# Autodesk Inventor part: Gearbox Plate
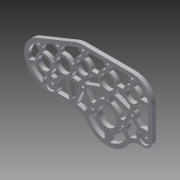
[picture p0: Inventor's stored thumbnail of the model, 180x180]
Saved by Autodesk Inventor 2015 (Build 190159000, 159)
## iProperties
Created: 2014-11
Part Number: Gearbox Plate
Material: Aluminum 6061
Document SubType Name: Sheet Metal
Designer: Michael
Density: 2.71 g/cm^3
Appearance: Aluminum - Flat
Sheet Metal Rule: Default
Mass: 155.766 g
Surface Area: 356.193 cm^2
Volume: 57.4784 cm^3
Author: Michael
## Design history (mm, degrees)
node "Face1"
  sketch "Sketch1" dims "d12" = 63.5 (= DrivenGear), "d35" = 22.352, "d96" = 4.2545 (derived)
    geometry: L1 (-39.37, 48.336)-(0, 48.336); L2 (0, 0)-(0, 48.336); L3 (0, 0)-(-38.1, 0); L4 (0, 48.336)-(-31.75, 48.336); L5 (-110.258, 47.105)-(-91.237, 0); L6 (-112.73, 53.228)-(-51.353, 78.012); L7 (-39.37, 80.34)-(39.37, 80.34); L8 (-100.747, 23.552)-(-39.37, 48.336); L9 (71.374, 48.336)-(71.374, 0); L10 (58.674, -12.7)-(52.771, -12.7); L11 (-91.237, -12.86)-(-52.655, -12.86); L12 (39.37, 80.34)-(-39.37, 80.34); L13 (-51.353, 78.012)-(-112.73, 53.228); L14 (-91.237, -12.86)-(-52.655, -12.86); L15 (58.674, -12.7)-(55.722, -12.7); L16 (71.374, 0)-(71.374, 48.336); L17 (-52.655, -12.86)-(-91.237, -12.86); L18 (52.771, -12.7)-(58.674, -12.7); L19 (-110.258, 47.105)-(-100.061, 21.852); L20 (-70.059, 35.944)-(-82.042, 65.62); L21 (-39.37, 48.336)-(-39.37, 73.736); L22 (-39.37, 48.336)-(-39.37, 22.936); L23 (0, 48.336)-(39.37, 48.336); L24 (39.37, 48.336)-(39.37, 73.736); L25 (39.37, 22.936)-(39.37, 48.336); L26 (39.37, 48.336)-(71.374, 48.336); L27 (0, 0)-(0, -39.688); L28 (-91.237, 0)-(-65.874, 25.581); L29 (-65.874, 25.581)-(-55.574, -12.86); L30 (-39.37, 22.936)-(-55.574, -12.86); L31 (39.37, 22.936)-(23.812, 0); L32 (-39.37, 22.936)-(-23.812, 0); L33 (-100.747, 23.552)-(-130.423, 11.569); L34 (-108.474, 35.267)-(-103.322, 37.348); L35 (-103.322, 37.348)-(-105.174, 41.934); L36 (-105.174, 41.934)-(-110.326, 39.853); L37 (-110.326, 39.853)-(-108.474, 35.267); L38 (-114.543, 20.978)-(-112.462, 15.826); L39 (-112.462, 15.826)-(-129.383, 8.993); L40 (-129.383, 8.993)-(-131.464, 14.145); L41 (-131.464, 14.145)-(-114.543, 20.978); L42 (-81.113, 6.266)-(-85.059, 10.178); L43 (-85.059, 10.178)-(-70.542, 24.819); L44 (-70.542, 24.819)-(-66.596, 20.907); L45 (-66.596, 20.907)-(-81.113, 6.266); L46 (-67.452, 20.736)-(-62.085, 22.174); L47 (-62.085, 22.174)-(-52.698, -12.86); L48 (-52.698, -12.86)-(-58.065, -14.298); L49 (-58.065, -14.298)-(-67.452, 20.736); L50 (-39.37, 73.99)-(39.37, 73.99); L51 (65.024, 0)-(65.024, 48.336); L52 (58.674, -6.35)-(52.771, -6.35); L53 (-91.237, -6.51)-(-52.655, -6.51); L54 (-115.367, 45.316)-(-48.975, 72.124); L55 (-58.623, -12.86)-(-53.562, -15.151); L56 (-53.562, -15.151)-(-39.601, 15.688); L57 (-39.601, 15.688)-(-44.663, 17.98); L58 (-44.663, 17.98)-(-58.623, -12.86); L59 (-89.033, 31.279)-(-86.952, 26.127); L60 (-86.952, 26.127)-(-83.093, 27.685); L61 (-83.093, 27.685)-(-85.173, 32.837); L62 (-85.173, 32.837)-(-89.033, 31.279); L63 (-78.318, 48.978)-(-73.166, 51.059); L64 (-73.166, 51.059)-(-79.466, 66.66)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; C1 r 25.4 at (0, 0); C2 r 22.86 at (0, 48.336); C3 r 7.62 at (-39.37, 48.336); C4 r 7.62 at (39.37, 48.336); C5 r 10.16 at (0, 48.336); C6 r 13.5 at (0, 0); C7 r 2.489 at (-91.237, 0); C8 r 2.489 at (-110.258, 47.105); C9 r 7.62 at (-100.747, 23.552); C10 r 25.4 at (-70.059, 35.944); C11 r 9.525 at (-91.237, 0); C12 r 9.779 at (-100.747, 23.552); C13 r 9.779 at (-39.37, 48.336); C14 r 9.779 at (39.37, 48.336); C15 r 11.176 at (0, 48.336); C16 r 14.351 at (0, 0); C17 r 9.525 at (58.674, 0); C18 r 2.489 at (-39.37, 22.936); C19 r 2.489 at (-39.37, 73.736); C20 r 2.489 at (39.37, 73.736); C21 r 2.489 at (39.37, 22.936); C22 r 2.489 at (58.674, 0); C23 r 2.489 at (-23.812, 0); C24 r 2.489 at (23.812, 0); C25 r 1.587 at (20.206, -6.735); C26 r 1.587 at (-20.206, -6.735); C27 r 1.587 at (0, 23.244); C28 r 2.489 at (0, 73.99); C29 r 2.489 at (-79.664, 59.732); C30 r 6.35 at (0, 73.99); C31 r 6.35 at (-79.664, 59.732); A1 r 38.1 centre (0, 0) between (-38.1, 0) and (-30.706, -22.555); A2 r 32.004 centre (-39.37, 48.336) between (-51.353, 78.012) and (-39.37, 80.34); A3 r 32.004 centre (39.37, 48.336) between (39.37, 80.34) and (71.374, 48.336); A4 r 32.004 centre (-100.747, 23.552) between (-112.73, 53.228) and (-125.169, 2.868); A5 r 12.7 centre (58.674, 0) between (58.674, -12.7) and (71.374, 0); A6 r 44.467 centre (-91.237, 31.607) between (-125.169, 2.868) and (-91.237, -12.86); A7 r 32.004 centre (-39.37, 48.336) between (-39.37, 80.34) and (-51.353, 78.012); A8 r 32.004 centre (-100.747, 23.552) between (-112.73, 53.228) and (-125.169, 2.868); A9 r 44.467 centre (-91.237, 31.607) between (-125.169, 2.868) and (-91.237, -12.86); A10 r 12.7 centre (58.674, 0) between (58.674, -12.7) and (71.374, 0); A11 r 32.004 centre (39.37, 48.336) between (71.374, 48.336) and (39.37, 80.34); A12 r 39.688 centre (0, 0) between (-32.107, -23.329) and (32.177, -23.232); A13 r 25.4 centre (-52.655, -38.26) between (-32.107, -23.329) and (-52.655, -12.86); A14 r 25.4 centre (52.771, -38.1) between (52.771, -12.7) and (32.177, -23.232); A15 r 25.4 centre (-52.655, -38.26) between (-32.107, -23.329) and (-52.655, -12.86); A16 r 39.687 centre (0, 0) between (-32.107, -23.329) and (32.177, -23.232); A17 r 25.4 centre (52.771, -38.1) between (52.771, -12.7) and (32.177, -23.232); A18 r 11.906 centre (-91.237, 0) between (-81.113, 6.266) and (-85.059, 10.178); A19 r 7.252 centre (-110.258, 47.105) between (-105.174, 41.934) and (-116.651, 43.682); A20 r 14.034 centre (-39.37, 48.336) between (-53.165, 45.762) and (-42.148, 62.092); A21 r 7.252 centre (-39.37, 73.736) between (-36.592, 67.038) and (-46.58, 72.956); A22 r 7.252 centre (39.37, 73.736) between (42.148, 67.038) and (32.123, 73.99); A23 r 14.034 centre (39.37, 48.336) between (25.614, 51.114) and (36.592, 62.092); A24 r 8.045 centre (-23.812, 0) between (-31.194, -3.199) and (-24.856, -7.977); A25 r 8.045 centre (23.812, 0) between (24.888, -7.973) and (31.207, -3.17); A26 r 12.7 centre (58.674, 0) between (53.185, 11.453) and (65.024, 10.999); A27 r 7.252 centre (39.37, 22.936) between (36.592, 29.635) and (42.148, 29.635); A28 r 25.654 centre (39.37, 48.336) between (65.024, 48.336) and (39.37, 73.99); A29 r 6.35 centre (58.674, 0) between (58.674, -6.35) and (65.024, 0); A30 r 31.75 centre (52.771, -38.1) between (52.771, -6.35) and (27.029, -19.515); A31 r 33.338 centre (0, 0) between (-26.97, -19.596) and (27.029, -19.515); A32 r 31.75 centre (-52.655, -38.26) between (-26.97, -19.596) and (-52.655, -6.51); A33 r 38.117 centre (-91.237, 31.607) between (-120.324, 6.972) and (-91.237, -6.51); A34 r 25.654 centre (-100.747, 23.552) between (-109.26, 47.753) and (-120.324, 6.972); A35 r 25.654 centre (-39.37, 48.336) between (-39.37, 73.99) and (-48.975, 72.124); A36 r 6.35 centre (-79.664, 59.732) between (-85.552, 57.355) and (-80.102, 53.397); A37 r 6.35 centre (0, 73.99) between (2.778, 68.28) and (-6.35, 73.99); A38 r 38.117 centre (-90.968, 31.526) between (-123.355, 11.427) and (-102.071, -4.938); A39 r 11.906 centre (-91.237, 0) between (-98.148, 9.695) and (-102.071, -4.938); A40 r 14.034 centre (-100.747, 23.552) between (-112.462, 15.826) and (-98.173, 9.757); A41 r 14.034 centre (-100.747, 23.552) between (-108.474, 35.267) and (-114.543, 20.978); A42 r 7.252 centre (-110.258, 47.105) between (-116.651, 43.682) and (-110.326, 39.853); A43 r 25.654 centre (-100.747, 23.552) between (-116.651, 43.682) and (-125.436, 16.58); A44 r 14.034 centre (-100.747, 23.552) between (-89.033, 31.279) and (-103.322, 37.348); A45 r 7.252 centre (-110.258, 47.105) between (-105.174, 41.934) and (-103.633, 50.054); A46 r 15.431 centre (-70.059, 35.944) between (-78.318, 48.978) and (-85.173, 32.837); A47 r 6.35 centre (-79.664, 59.732) between (-85.552, 57.355) and (-80.102, 53.397); A48 r 14.034 centre (-100.747, 23.552) between (-93.021, 11.837) and (-86.952, 26.127); A49 r 15.431 centre (-70.059, 35.944) between (-83.093, 27.685) and (-74.239, 21.091); A50 r 11.906 centre (-91.237, 0) between (-85.059, 10.178) and (-92.996, 11.776); A51 r 11.906 centre (-91.237, 0) between (-81.268, -6.51) and (-81.113, 6.266); A52 r 15.431 centre (-70.059, 35.944) between (-57.025, 44.203) and (-73.166, 51.059); A53 r 6.35 centre (-79.664, 59.732) between (-74.95, 55.478) and (-73.776, 62.11); A54 r 14.034 centre (-39.37, 48.336) between (-42.148, 62.092) and (-53.165, 45.762); A55 r 7.252 centre (-39.37, 73.736) between (-46.58, 72.956) and (-42.148, 67.038); A56 r 14.034 centre (-39.37, 48.336) between (-51.085, 40.61) and (-42.148, 34.58); A57 r 15.431 centre (-70.059, 35.944) between (-57.726, 26.671) and (-54.944, 39.051); A58 r 7.252 centre (-39.37, 22.936) between (-42.148, 29.635) and (-45.915, 26.058); A59 r 31.75 centre (-52.655, -38.26) between (-36.862, -10.717) and (-49.712, -6.647); A60 r 7.252 centre (-39.37, 22.936) between (-39.601, 15.688) and (-39.184, 15.687); A61 r 8.045 centre (-23.812, 0) between (-30.35, 4.689) and (-31.194, -3.199); A62 r 7.252 centre (-39.37, 22.936) between (-46.203, 20.509) and (-44.663, 17.98); A63 r 14.034 centre (-39.37, 48.336) between (-25.614, 51.114) and (-36.592, 62.092); A64 r 15.431 centre (0, 48.336) between (-2.778, 63.515) and (-15.178, 51.114)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; 17 further points; 1 other entity
    constraints: 434 end point, 251 point on circle, 132 centre point, 73 parallel, 56 tangent, 53 perpendicular, 51 point on line, 47 coincident, 44 concentric, 42 collinear, 9 midpoint, 7 vertical alignment, 4 horizontal alignment, 4 symmetric about line, 3 equal length, 3 equal radius, 3 vertical, 2 horizontal, 99 other
    dimensions: "d1" = 50.8 diameter of C1 (= HSpeed2); "d2" = 45.72 diameter of C2 (= HSpeed1); "d5" = 15.24 diameter of C3 (= CIMgear); "d7" = 15.24 diameter of C4 (= CIMgear); "d10" = 20.32 diameter of C5 (= LSpeed1); "d11" = 76.2 diameter of A1 (= LSpeed2); "d13" = 27.0002 diameter of C6 (derived); "d16" = 0 distance between parallel lines of L1 L4; "d17" = 64.008 diameter of A2 (= CIM); "d18" = 64.008 diameter of A3 (= CIM); "d19" = 64.008 diameter of A4 (= CIM); "d20" = 4.9784 diameter of C7; "d21" = 4.9784 diameter of C8 (derived); "d22" = 25.4 distance of L5.start L8.start; "d23" = 15.24 diameter of C9 (= CIMgear); "d24" = 50.8 diameter of C10 (= InterGear); "d29" = 12.7 radius of A5; "d30" = 19.05 diameter of C11; "d34" = 19.558 diameter of C12 (derived); "d36" = 19.558 diameter of C13; "d37" = 19.558 diameter of C14 (derived); "d38" = 22.352 diameter of C15; "d39" = 28.702 diameter of C16; "d40" = 19.05 diameter of C17; "d41" = 4.9784 diameter of C18 (derived); "d42" = 4.9784 diameter of C19 (derived); "d43" = 4.9784 diameter of C20 (derived); "d44" = 4.9784 diameter of C21 (derived); "d49" = 4.9784 diameter of C22 (derived); "d59" = 79.375 diameter of A12 (derived); "d60" = 25.4 radius of A13; "d61" = 25.4 radius of A14; "d89" = 4.2545 dimension on C12; "d90" = 2.38125 radial gap between concentric circles of C11 A18; "d91" = 4.7625 radial gap between concentric circles of A19 C8; "d92" = 4.9784 diameter of C23; "d93" = 4.9784 diameter of C24 (derived); "d94" = 23.8125 distance of L27.start C23.centre; "d95" = 23.8125 distance of C24.centre point (0, 0) (derived); "d99" = 4.7625 dimension on C18 (derived); "d100" = 4.2545 radial gap between concentric circles of C13 A20 (derived); "d101" = 4.2545 dimension on C15 (derived); "d102" = 4.2545 radial gap between concentric circles of C14 A23 (derived); "d103" = 4.7625 radial gap between concentric circles of C19 A21 (derived); "d104" = 4.7625 radial gap between concentric circles of C20 A22 (derived); "d105" = 4.7625 radial gap between concentric circles of C21 A27 (derived); "d106" = 5.55625 radial gap between concentric circles of C24 A25 (derived); "d107" = 5.55625 radial gap between concentric circles of A24 C23 (derived); "d108" = 7.9375 dimension on C16; "d109" = 3.175 radial gap between concentric circles of A26 C17; "d110" = 5.55625 distance between parallel lines of L35 L37; "d111" = 5.55625 distance between parallel lines of L39 L41 (derived); "d112" = 5.55625 distance between parallel lines of L43 L45 (derived); "d113" = 5.55625 distance between parallel lines of L47 L49 (derived); "d114" = 6.35 distance between parallel lines of L6 L54; "d115" = 5.55625 distance between parallel lines of L58 L56 (derived); "d116" = 5.55625 distance between parallel lines of L62 L60 (derived); "d117" = 5.55625 distance between parallel lines of L64 L66 (derived); "d118" = 5.55625 distance between parallel lines of L70 L68 (derived); "d119" = 5.55625 distance between parallel lines of L74 L72 (derived); "d120" = 5.55625 distance between parallel lines of L76 L78 (derived); "d122" = 20.20558 horizontal distance of C25.centre point (0, 0); "d123" = 6.73519 vertical distance of point (0, 0) C25.centre; "d124" = 3.175 diameter of C25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
feature "Corner Round1" dims "d160" = 1.5875
hole "Hole1" diameter "d163" = 19.05; stored, may be unused: countersink angle "d167" = 82 deg, drill point angle "d169" = 0 deg; dims "d161" = 25.4, "d162" = 25.4, "d164" = 19.05, "d165" = 9.525, "d166" = 6.35, "d168" = 3.175
hole "Hole2" diameter "d172" = 19.05; stored, may be unused: countersink angle "d176" = 82 deg, drill point angle "d178" = 0 deg; dims "d170" = 25.4, "d171" = 25.4, "d173" = 19.05, "d174" = 9.525, "d175" = 6.35, "d177" = 3.175
body "Solid1"
face "Plate1" dims "Thickness" = 6.35 (derived)
other parameters: "CIMgear" = 15.24 [user parameter; used in 3 equation terms], "DrivenGear" = 63.5 [user parameter; used in 1 equation term], "HSpeed1" = 45.72 [user parameter; used in 1 equation term], "HSpeed2" = 50.8 [user parameter; used in 1 equation term], "LSpeed1" = 20.32 [user parameter; used in 1 equation term], "LSpeed2" = 76.2 [user parameter; used in 1 equation term], "CIM" = 64.008 [user parameter; used in 3 equation terms], "InterGear" = 50.8 [user parameter; used in 1 equation term], "KFactor" = 4.4, "BendRadius" = 6.35 (derived), "BendReliefWidth" = 6.35 (derived), "BendReliefDepth" = 3.175 (derived), "CornerReliefSize" = 25.4 (derived), "SeamGap" = 0.00508, "MinimumRemnant" = 12.7 (derived), "TransitionRadius" = 6.35 (derived), "JacobiRadiusSize" = 6.35 (derived), "GapSize" = 6.35 (derived), "d50" = 6.35 (derived), "Stage2Distance" = 48.3362 [user parameter], "StageInterDistance" = 33.0962 [user parameter], "Dog" = 27.0002 [user parameter]
